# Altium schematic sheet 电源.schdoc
size 420 x 297 mm; Symbol: Drawing-Symbol_A4; Company: 嘉立创EDA; Version: V1.0; Page Size: A4; @Project Name: FOC; @Update Date: 2026-07-14; @Create Date: 2026-07-14; Device: Drawing-Symbol_A4; @Board Name: Board1; @Page Name: P1; @Create Time: 03:45:48; @Page Count: 1; @Page No: 1; @Schematic Name: Schematic1; @Update Time: 03:45:48; @Assembly Variant: Basic; Border: 1; Title Block Position: 3; Size: A4; Width: 1655; Height: 1170; Region Start: 1; X Region Count: 6; Y Region Count: 4; Blade Width: 10
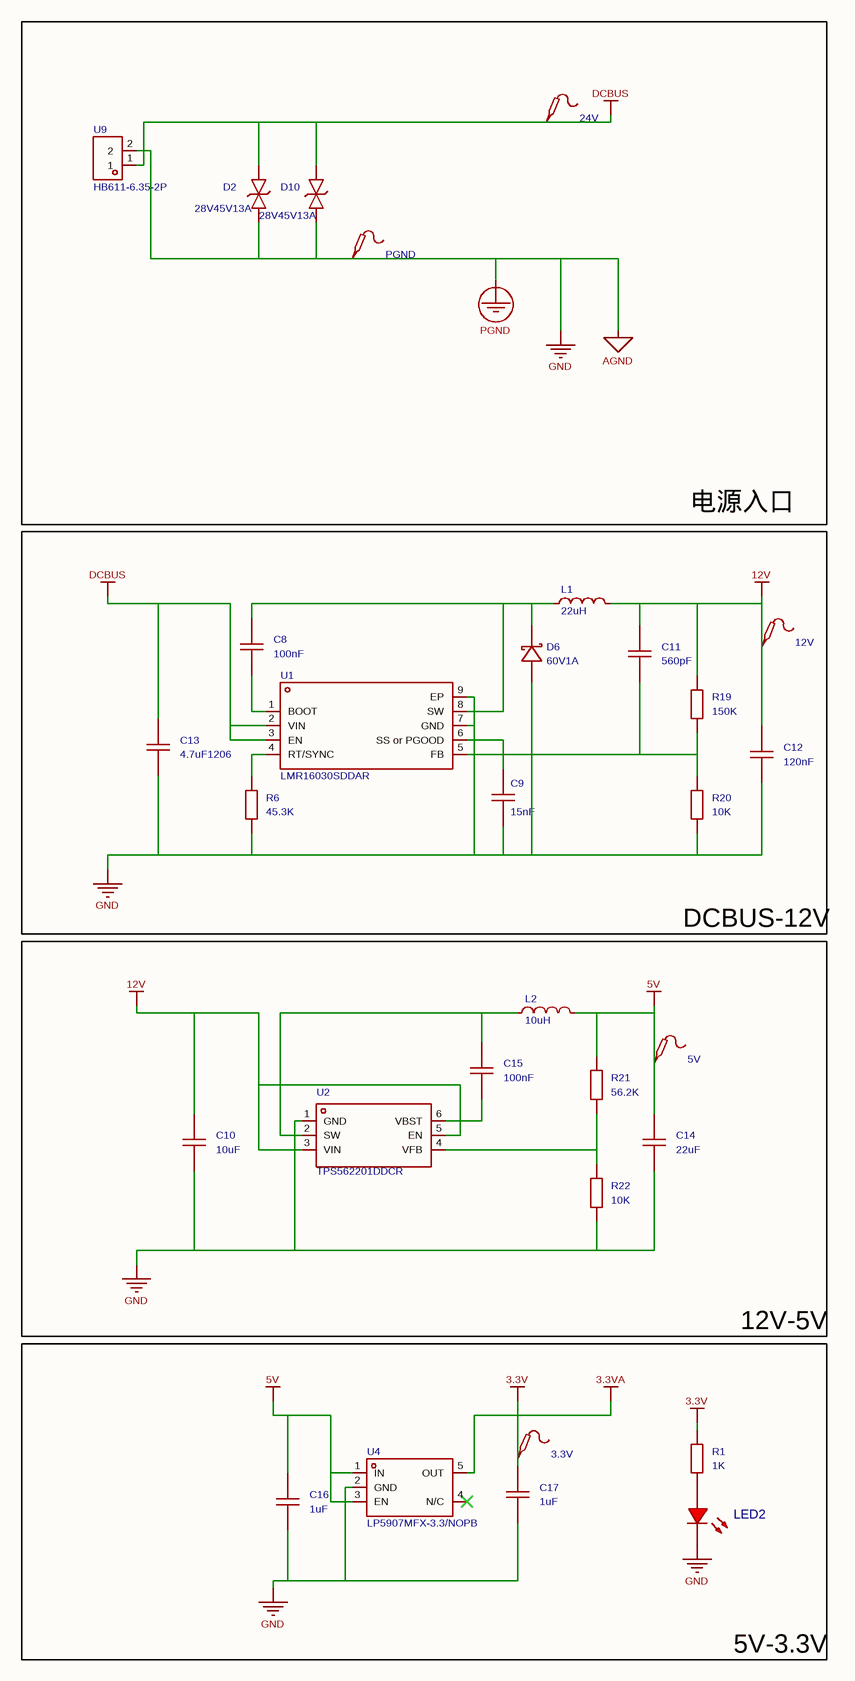
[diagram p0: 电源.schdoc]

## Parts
3.3V  (no value)  [Test-Point-0.5mm]
5V  (no value)  [Test-Point-0.5mm]
12V  (no value)  [Test-Point-0.5mm]
24V  (no value)  [Test-Point-0.5mm]
C8  100nF  [C0603]
C9  15nF  [C0603]
C10  10uF  [C0603]
C11  560pF  [C0603]
C12  120nF  [C0603]
C13  4.7uF1206  [C1206]
C14  22uF  [C0603]
C15  100nF  [C0603]
C16  1uF  [C0603]
C17  1uF  [C0603]
D2  28V45V13A  [SMB_L4.6-W3.6-LS5.4-BI]
D6  60V1A  [SOD-323_L1.7-W1.3-LS2.5-FD]
D10  28V45V13A  [SMB_L4.6-W3.6-LS5.4-BI]
L1  22uH  [IND-SMD_L5.5-W5.2]
L2  10uH  [IND-SMD_L4.4-W4.2]
LED2  (no value)  [LED_0603]
PGND  (no value)  [Test-Point-0.5mm]
R1  1K  [R0603]
R6  45.3K  [R0603]
R19  150K  [R0603]
R20  10K  [R0603]
R21  56.2K  [R0603]
R22  10K  [R0603]
U1  LMR16030SDDAR  [SOIC-8_L4.9-W3.9-P1.27-LS6.0-BL-EP2.3]
U2  TPS562201DDCR  [SOT-23-6_L2.9-W1.6-P0.95-LS2.8-BR]
U4  LP5907MFX-3.3/NOPB  [SOT-23-5_L3.0-W1.7-P0.95-LS2.8-BR]
U9  HB611-6.35-2P  [CONN-TH_HB611-6.35-2P]

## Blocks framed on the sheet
电源入口: 24V D2 D10 PGND U9

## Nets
3.3V: 3.3V.1 C17.2 R1.2 U4.5(OUT)  [also labelled 3.3VA]
5V: 5V.1 C14.2 C16.2 L2.2 R21.2 U4.1(IN) U4.3(EN)
12V: 12V.1 C10.2 C11.2 C12.2 L1.2 R19.2 U2.3(VIN) U2.5(EN)
AGND: C9.1 C10.1 C12.1 C13.1 C14.1 C16.1 C17.1 D2.1 D6.1(A) D10.1 LED2.1(C) PGND.1 R6.1 R20.1 R22.1 U1.7(GND) U1.9(EP) U2.1(GND) U4.2(GND) U9.2  [also labelled GND, PGND]
DCBUS: 24V.1 C13.2 D2.2 D10.2 U1.2(VIN) U1.3(EN) U9.1
NetC8_1: C8.1 U1.1(BOOT)
NetC8_2: C8.2 D6.2(K) L1.1 U1.8(SW)
NetC9_2: C9.2 U1.6(SS_or_PGOOD)
NetC11_1: C11.1 R19.1 R20.2 U1.5(FB)
NetC15_1: C15.1 U2.6(VBST)
NetC15_2: C15.2 L2.1 U2.2(SW)
NetLED2_2: LED2.2(A) R1.1
NetR6_2: R6.2 U1.4(RT/SYNC)
NetR21_1: R21.1 R22.2 U2.4(VFB)

Not connected (* = marked no-connect by the designer): U4 4(N/C)*

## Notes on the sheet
- DCBUS-12V
- 12V-5V
- 5V-3.3V

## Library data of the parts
3.3V 5V 12V 24V PGND = Test-Point: Test Point 测试点; AddInBom: yes
C8-C12 C14-C17 = CAP_0603: Symbol: Capacitance; 3D Model: ac125912035d415993ca9572d50418b10819f05c4eef4c71ace90d822a990e87; 3D Model Transform: 62.992,31.496,0,0,0,0,0,0,0; ConvertToPcb: yes; ModelName: C0603_L1.6-W0.8-H0.8
C13 = CAP_1206: Symbol: Capacitance; 3D Model: e4be705b945545a48e666415e3682bd80819f05c4eef4c71ace90d822a990e87; 3D Model Transform: 125.984,62.992,0,0,0,0,0,0,0; ConvertToPcb: yes; ModelName: C1206_L3.2-W1.6-H1.3
D2 = SMBJ28CA_C19077583: 极性:双向;反向截止电压(Vrwm):28V;钳位电压:45.4V;峰值脉冲电流(Ipp):13.22A@10/1000us;峰值脉冲功率(Ppp):600W@10/1000us;击穿电压:34.4V;; Manufacturer: R+O(宏嘉诚); AddInBom: yes; ModelId: 56a671846d664f15ac0751d5510bb56a0819f05c4eef4c71ace90d822a990e87; ModelTransform: 212.598,142.5194,0,0,0,0,0,0,0; Polarity: 双向; Reverse Stand-Off Voltage (Vrwm): 28V; Clamping Voltage: 45.4V; Voltage - Breakdown: 34.4V; Reverse Leakage Current (Ir): 5uA; level of protection: IEC 61000-4-2; Type: TVS
D6 = B16WS_C7420327: 二极管配置:独立式;正向压降(Vf):700mV@1A;直流反向耐压(Vr):60V;整流电流:1A;; Manufacturer: R+O(宏嘉诚); AddInBom: yes; ModelId: 0f2f330c645944df9245ac3c3fec34560819f05c4eef4c71ace90d822a990e87; ModelTransform: 98.425,49.2125,0,180,0,0,0,0,0; Diode Configuration: 独立式; Voltage - DC Reverse(Vr): 60V; Current - Rectified: 1A; Reverse Leakage Current (Ir): 100uA@60V; Operating Junction Temperature Range: -55℃~+150℃; Non-Repetitive Peak Forward Surge Current: 10A
D10 = SMBJ28CA_C19077583: 极性:双向;反向截止电压(Vrwm):28V;钳位电压:45.4V;峰值脉冲电流(Ipp):13.22A@10/1000us;峰值脉冲功率(Ppp):600W@10/1000us;击穿电压:34.4V;; Manufacturer: R+O(宏嘉诚); 3D Model: 56a671846d664f15ac0751d5510bb56a0819f05c4eef4c71ace90d822a990e87; 3D Model Transform: 212.598,142.5194,0,0,0,0,0,0,0; Polarity: 双向; Reverse Stand-Off Voltage (Vrwm): 28V; Clamping Voltage: 45.4V; Voltage - Breakdown: 34.4V; Reverse Leakage Current (Ir): 5uA; level of protection: IEC 61000-4-2; Type: TVS; AddInBom: yes
L1 = SMMS0530-220M: 电感值:22uH;精度:±20%;额定电流:1.8A;饱和电流(Isat):2A;类型:-;; Manufacturer: SXN(顺翔诺); AddInBom: yes; ModelId: 8807b4a3401f4609bbc4ad95ff9613320819f05c4eef4c71ace90d822a990e87; ModelName: IND-SMD_L5.5-W5.2-H3.0; ModelTransform: 216.535,204.724,0,0,0,0,0,0,0; Tolerance: ±20%; Current Rating: 1.8A; Current - Saturation(Isat): 2A; DC Resistance(DCR): 394.8mΩ
L2 = FXL0420-100-M: 电感值:10uH;精度:±20%;额定电流:1.6A;饱和电流(Isat):2.2A;类型:一体成型电感;; Manufacturer: cjiang(长江微电); AddInBom: yes; ModelId: e9b3d3f4fa134185b54d517730715f160819f05c4eef4c71ace90d822a990e87; ModelName: IND-SMD_L4.2-W4.4-H2.0; ModelTransform: 173.228,165.354,0,0,0,0,0,0,0; Tolerance: ±20%; Current Rating: 1.6A; Current - Saturation(Isat): 2.2A; DC Resistance(DCR): 282mΩ; Type: 一体成型电感
LED2 = LED_0603-R: Symbol: LED_R; Convert to PCB: yes; 3D Model: dd8257b0d61a4cd7b68939a056e080950819f05c4eef4c71ace90d822a990e87; 3D Model Transform: 58.72,29.4,22.03,0,0,0,0,0,0; ModelName: LED-0603_R
R1 R6 R19-R22 = Res_0603: Symbol: 电阻; 3D Model: fc143cca1e79419f9cd78b61e9279f080819f05c4eef4c71ace90d822a990e87; 3D Model Transform: 31.8897,63.7794,0,90,0,0,0,0,0; ConvertToPcb: yes
U1 = LMR16030SDDAR: 功能类型:降压型;工作电压:4.3V~60V;输出电压:800mV~50V;输出电流:3A;输出类型:可调;; Manufacturer: TI(德州仪器); AddInBom: yes; ModelId: ba240e69e1f440f79b85bd6e5ae1d4fa0819f05c4eef4c71ace90d822a990e87; ModelTransform: 192.913,236.22,0,0,0,0,0,0,0; Function: 降压型; Output Current: 3A; Frequency - Switching: 2.5MHz; Synchronous Rectifier: 否; Number of Outputs: 1; Topology: 降压式; Quiescent Current: 40uA; Switch tube (built-in/external): 内置; Output Type: 可调
U2 = TPS562201DDCR: 功能类型:降压型;工作电压:4.5V~17V;输出电压:768mV~7V;输出电流:2A;输出类型:可调;; Manufacturer: TI(德州仪器); AddInBom: yes; ModelId: 18da8f6c14a34920b3e136b5c401a1190819f05c4eef4c71ace90d822a990e87; ModelName: SOT-23-6_L2.9-W1.6-H1.5-LS2.8-P0.95; ModelTransform: 110.73671,114.173,0,180,0,0,0.001,-0.003,0; Function: 降压型; Output Current: 2A; Frequency - Switching: 580kHz; Synchronous Rectifier: 是; Number of Outputs: 1; Topology: 降压式; Quiescent Current: 380uA; Switch tube (built-in/external): 内置; Output Type: 可调
U4 = LP5907MFX-3.3/NOPB: 输出极性:正极;工作电压:5.5V;输出电压:3.3V;输出电流:250mA;电源纹波抑制比(PSRR):82dB@(1kHz);输出类型:固定;; Manufacturer: TI(德州仪器); AddInBom: yes; ModelId: 0a2a1b8f50944f73965918ad6e5fe1670819f05c4eef4c71ace90d822a990e87; ModelName: SOT-23-5_L2.9-W1.6-H1.1-LS2.8-P0.95; ModelTransform: 114.173,109.636,0,180,0,0,0,0,0; Output Configuration: 正极; Voltage - Supply: 5.5V; Output Voltage: 3.3V; Output Current: 250mA; Voltage Dropout: 250mV@(250mA); standby current: 12uA; Noise: 10uVrms; Output Type: 固定; Number of Outputs: 1
U9 = HB611-6.35-2P: 隔板类型:三面;间距:6.35mm;结构:1x2P;安装方式:直插;引脚位置:边脚;排数:1;每排PIN数:2;额定电流:24A;额定电压:450V;线规 - AWG:12~22;线规 - 平方毫米:2.5;工作温度:-40℃~+105℃;颜色:黑色;; Manufacturer: KEFA(科发); 3D Model: e2f1636713fc405d97dd517b238e59c60819f05c4eef4c71ace90d822a990e87; 3D Model Transform: 547.243,562.991,0,0,0,0,0,-104.331,-165.354; Barrier Type: 三面; Pitch: 6.35mm; Number of Positions or Pins: 1x2P; Pin Location: 边脚; Number of PINs Per Row: 2; Current Rating: 24A; Voltage Rating (Max): 450V; Wire Gauge - AWG: 12~22; Wire Gauge - mm2: 2.5; AddInBom: yes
